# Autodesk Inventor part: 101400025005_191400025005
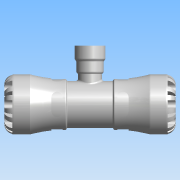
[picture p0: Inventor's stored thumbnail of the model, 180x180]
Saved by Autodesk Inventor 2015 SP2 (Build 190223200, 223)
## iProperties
Created: 2016-12
Part Number: 101400025005_191400025005
Material: PVC-Piping
Description: PLASSON TEE WITH THREADED FEMALE OFFTAKE 25X1/2" SERIES 1
Document SubType Name: Modeling
Designer: KIM
Mass: 664.223 g
Surface Area: 733.008 cm^2
Volume: 474.445 cm^3
Density: 1.4 g/cm^3
Appearance: Smooth - White
Author: KIM
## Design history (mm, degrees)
derived "1014.ipt"
feature "Solid1::1014.ipt"
tag "TaggingFeature1"
body "Solid1"
other parameters: "d1" = 20.16, "d2" = 25, "d3" = 31.25, "d4" = 47, "d8" = 39.95, "d13" = 6.3, "d14" = 6.3, "d15" = 0, "d17" = 360 deg, "d19" = 8 deg, "d20" = 0.5, "d21" = 0.5, "d22" = 8 deg, "d24" = 0, "d26" = 360 deg, "d33" = 4.7, "d43" = 36.66, "d51" = 0.47, "d54" = 8.75, "d55" = 5.5, "d57" = 12.348, "d58" = 0, "d74" = 0, "d77" = 2.08333, "d78" = 48, "d79" = 36.66, "d80" = 134, "d82" = 0.5, "d115" = 360 deg, "d139" = 6.3, "d140" = 0, "d142" = 360 deg, "d207" = 90 deg, "d228" = 7.4375, "d247" = 0.94, "d248" = 2.88, "d266" = 0, "d268" = 18.631, "d270" = 2.79465, "d271" = 5.66667, "d274" = 1.39733, "d275" = 46, "d276" = 1.8631, "d277" = 1.8631, "d278" = 1.8631, "d279" = 1.8631, "d281" = 0, "d282" = 17, "d_" = 25, "E_" = 47, "l_" = 48, "A_" = 46, "H_" = 134, "Rp_" = 18.631, "l_2" = 17, "d9" = 7.875, "d11" = 47, "d12" = 31.25
